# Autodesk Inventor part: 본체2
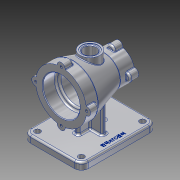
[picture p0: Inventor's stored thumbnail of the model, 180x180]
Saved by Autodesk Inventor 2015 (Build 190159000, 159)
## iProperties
Created: 2020-12
Part Number: 본체2
Material: 알루미늄 6061
Document SubType Name: Modeling
Designer: Lineart
Density: 2.7 g/cm^3
Appearance: 알루미늄 - 평지
Mass: 1030.13 g
Surface Area: 850.653 cm^2
Volume: 381.528 cm^3
Author: Lineart
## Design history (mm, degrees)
sketch "스케치1"
  geometry: L1 (-50, 0)-(50, 0); L2 (-50, 0)-(-50, 44); L3 (-50, 44)-(-30, 44); L4 (-30, 44)-(25, 27.5); L5 (25, 27.5)-(50, 27.5); L6 (50, 27.5)-(50, 0); 2 further points
  constraints: 12 end point, 2 perpendicular, 1 coincident, 1 horizontal, 1 midpoint, 1 parallel, 1 vertical
  dimensions: "d1" = 88 diameter of L3 L1; "d2" = 55 diameter of L5 L1; "d4" = 100 distance between parallel lines of L6 L2; "d5" = 20 distance from line of L3.end L2; "d158" = 25 distance from line of L4.end L6
revolve "회전1" sketch "스케치1" stored, may be unused: angle "d7" = 90 deg
node "작업 평면1"
node "작업 평면2"
sketch "스케치3"
  geometry: L1 (-65, -50)-(65, -50); L2 (65, -50)-(65, 50); L3 (65, 50)-(-65, 50); L4 (-65, 50)-(-65, -50); L5 (-65, -50)-(65, 50); L6 (65, -50)-(-65, 50); 1 further point
  constraints: 12 end point, 2 midpoint, 2 parallel, 1 horizontal, 1 perpendicular
  dimensions: "d9" = 130 distance of L3.end L2.end; "d10" = 100 distance of L2.end L1.end
extrude "돌출1" join sketch "스케치3" distance "d11" = 12; taper "d12" = 0 deg
sketch "스케치5"
  geometry: L1 (0, -4)-(0, 4); L2 (24, 0)-(-24, 0); L3 (-65, -50)-(-65, 50) reference; L4 (65, -50)-(-65, -50) reference; L5 (24, -4)-(24, 4); L6 (-24, -4)-(-24, 4); L7 (24, -4)-(-24, -4); L8 (24, 4)-(-24, 4); 1 further point
  constraints: 12 end point, 4 midpoint, 4 parallel
  dimensions: "d15" = 65 distance between parallel lines of L3 L1; "d16" = 50 distance between parallel lines of L2 L4; "d17" = 24 distance between parallel lines of L1 L5; "d18" = 24 distance between parallel lines of L1 L6; "d19" = 4 distance between parallel lines of L2 L7; "d20" = 4 distance between parallel lines of L2 L8
extrude "돌출2" join sketch "스케치5" distance "d21" = 67.5; taper "d22" = 0 deg
node "작업 평면4"
sketch "스케치6"
  geometry: L1 (-62.176, 4)-(12, 4); L2 (-62.176, -21)-(12, -21); L3 (-62.176, 29)-(12, 29); L4 (12, -46)-(12, 54) reference; L5 (-62.176, -21)-(-62.176, 29); L6 (12, -21)-(12, 29); 1 further point
  constraints: 10 end point, 2 midpoint, 2 parallel, 2 point on line, 1 collinear, 1 horizontal, 1 vertical
  dimensions: "d23" = 25 distance between parallel lines of L1 L2; "d24" = 25 distance between parallel lines of L1 L3; "d25" = 50 distance of L3.end L2.end (derived); "d26" = 74.17552 distance between parallel lines of L4 L5; "d27" = 25 distance from line of L4.end L3
extrude "돌출3" join sketch "스케치6" stored distance "d28" = 8; taper "d29" = 0 deg
sketch "스케치7"
  geometry: L1 (50, 0)-(-50, 0); L2 (50, 44)-(50, -44) reference; L3 (50, 0)-(50, -32); L4 (50, -32)-(30, -32); L5 (27, -29)-(27, -29); L6 (24, -26)-(-17, -26); L7 (-20, -23)-(-20, -23); L8 (-50, 27.5)-(-50, -27.5) reference; L9 (-23, -20)-(-50, -20); L10 (-50, -20)-(-50, 0); A1 r 3 centre (30, -29) between (27, -29) and (30, -32); A2 r 3 centre (24, -29) between (27, -29) and (24, -26); A3 r 3 centre (-17, -23) between (-20, -23) and (-17, -26); A4 r 3 centre (-23, -23) between (-20, -23) and (-23, -20); 1 further point
  constraints: 16 end point, 8 point on circle, 8 tangent, 4 centre point, 4 perpendicular, 3 equal radius, 2 horizontal, 2 midpoint, 2 point on line
  dimensions: "d30" = 64 diameter of L4 L1; "d31" = 52 diameter of L6 L1; "d33" = 23 distance between parallel lines of L5 L2; "d34" = 47 distance between parallel lines of L7 L5; "d36" = 40 diameter of L9 L1; "d37" = 30 distance between parallel lines of L8 L7 (derived); "d38" = 3 radius of A1
revolve "회전2" sketch "스케치7" stored, may be unused: angle "d39" = 90 deg
sketch "스케치8"
  geometry: C1 r 7 at (-44, 0); C2 r 7 at (0, -44); C3 r 7 at (44, 0); C4 r 7 at (0, 44); A1 r 44 centre (0, 0) between (-44, 0) and (0, 44) reference; 3 further points
  constraints: 4 centre point, 4 coincident, 4 point on circle, 2 horizontal alignment, 2 vertical alignment
  dimensions: "d40" = 7 radius of C1; "d41" = 7 radius of C2; "d42" = 7 radius of C3; "d45" = 7 radius of C4
extrude "돌출4" join sketch "스케치8" distance "d46" = 15; taper "d47" = 0 deg
sketch "스케치9"
  geometry: C1 r 7 at (27.5, 0); C2 r 7 at (0, 27.5); C3 r 7 at (-27.5, 0); C4 r 7 at (0, -27.5); A1 r 27.5 centre (0, 0) between (27.5, 0) and (0, 27.5) reference; A2 r 27.5 centre (0, 0) between (27.5, 0) and (0, 27.5) reference; 3 further points
  constraints: 8 point on circle, 4 centre point, 4 coincident, 2 horizontal alignment, 2 vertical alignment
  dimensions: "d48" = 7 radius of C1; "d49" = 7 radius of C2; "d50" = 7 radius of C3; "d51" = 7 radius of C4
extrude "돌출5" join sketch "스케치9" distance "d52" = 15; taper "d53" = 0 deg
hole "구멍1" diameter "d56" = 4.134; stored, may be unused: countersink angle "d60" = 90 deg, drill point angle "d62" = 118 deg; dims "d54" = 10, "d55" = 10, "d57" = 9, "d58" = 4, "d59" = 2, "d61" = 11
hole "구멍2" diameter "d65" = 4.134; stored, may be unused: countersink angle "d69" = 90 deg, drill point angle "d71" = 118 deg; dims "d63" = 10, "d64" = 10, "d66" = 9, "d67" = 4, "d68" = 2, "d70" = 11
hole "구멍3" diameter "d74" = 4.134; stored, may be unused: countersink angle "d78" = 90 deg, drill point angle "d80" = 118 deg; dims "d72" = 10, "d73" = 10, "d75" = 9, "d76" = 4, "d77" = 2, "d79" = 11
hole "구멍4" diameter "d83" = 4.134; stored, may be unused: countersink angle "d87" = 90 deg, drill point angle "d89" = 118 deg; dims "d81" = 10, "d82" = 10, "d84" = 9, "d85" = 4, "d86" = 2, "d88" = 11
hole "구멍5" diameter "d92" = 4.134; stored, may be unused: countersink angle "d96" = 90 deg, drill point angle "d98" = 118 deg; dims "d90" = 10, "d91" = 10, "d93" = 9, "d94" = 4, "d95" = 2, "d97" = 11
hole "구멍6" diameter "d101" = 4.134; stored, may be unused: countersink angle "d105" = 90 deg, drill point angle "d107" = 118 deg; dims "d99" = 10, "d100" = 10, "d102" = 9, "d103" = 4, "d104" = 2, "d106" = 11
hole "구멍7" diameter "d110" = 4.134; stored, may be unused: countersink angle "d114" = 90 deg, drill point angle "d116" = 118 deg; dims "d108" = 10, "d109" = 10, "d111" = 9, "d112" = 4, "d113" = 2, "d115" = 11
hole "구멍8" diameter "d119" = 4.134; stored, may be unused: countersink angle "d123" = 90 deg, drill point angle "d125" = 118 deg; dims "d117" = 10, "d118" = 10, "d120" = 9, "d121" = 4, "d122" = 2, "d124" = 11
fillet "모깎기1" dims "d126" = 12
fillet "모깎기2" dims "d127" = 3
sketch "스케치11"
  geometry: C1 r 5 at (53, -38); C2 r 5 at (53, 38); C3 r 5 at (-53, 38); C4 r 5 at (-53, -38); A1 r 12 centre (53, -38) between (53, -50) and (65, -38) reference; A2 r 12 centre (53, 38) between (65, 38) and (53, 50) reference; A3 r 12 centre (-53, 38) between (-53, 50) and (-65, 38) reference; A4 r 12 centre (-53, -38) between (-65, -38) and (-53, -50) reference; 1 further point
  constraints: 4 centre point, 4 coincident
  dimensions: "d128" = 10 diameter of C1; "d129" = 10 diameter of C2; "d130" = 10 diameter of C3; "d131" = 10 diameter of C4
extrude "돌출6" cut sketch "스케치11" stored distance "d132" = 15; taper "d133" = 0 deg
fillet "모깎기3" dims "d134" = 3
fillet "모깎기4" dims "d135" = 3
fillet "모깎기5" dims "d136" = 3
fillet "모깎기6" dims "d137" = 3
node "작업 평면5"
sketch "스케치13"
  geometry: C1 r 17 at (0, 0); 1 further point
  constraints: 1 centre point, 1 coincident
  dimensions: "d139" = 34 diameter of C1
extrude "돌출7" join sketch "스케치13" distance "d140" = 18.25; taper "d141" = 0 deg
sketch "스케치14"
  geometry: C1 r 14 at (0, 0); 1 further point
  constraints: 1 centre point, 1 coincident
  dimensions: "d142" = 28 diameter of C1
extrude "돌출8" cut sketch "스케치14" distance "d143" = 1; taper "d144" = 0 deg
sketch "스케치15"
  geometry: C1 r 11 at (0, 0); 1 further point
  constraints: 1 centre point, 1 coincident
  dimensions: "d145" = 22 diameter of C1
extrude "돌출9" cut sketch "스케치15" distance "d146" = 36; taper "d147" = 0 deg
fillet "모깎기7" dims "d148" = 3
fillet "모깎기8" dims "d149" = 1
fillet "모깎기9" dims "d150" = 1
chamfer "모따기1" distance "d151" = 1; stored, may be unused: second distance "d152" = 2, angle "d153" = 45 deg
fillet "모깎기10" dims "d154" = 1
sketch "스케치16"
  geometry: L1 (53, 50)-(-53, 50) reference; 2 further points
  constraints: 1 vertical alignment, 1 other
  dimensions: "d155" = 10 vertical distance of L1.start point (0, 40)
feature "엠보싱1" sketch "스케치16" dims "d156" = 0.5, "d157" = 0
node "솔리드1"
